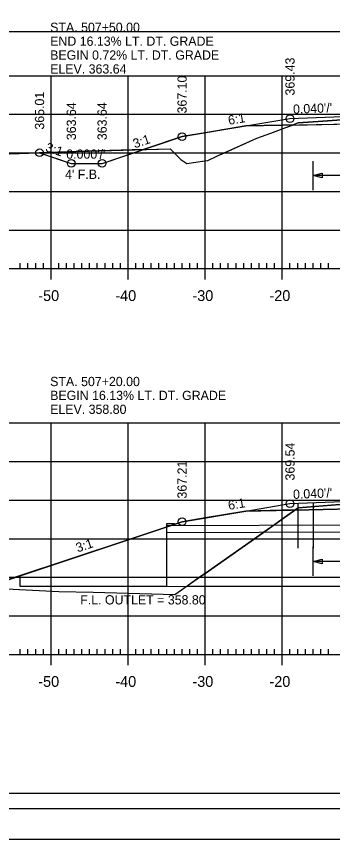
# Model space of a CAD drawing. Extents: x 1368910 to 1369601, y 380116 to 380950.
# Drawn here: x 1369025.7 to 1369066.8, y 380523.8 to 380630.4 of the extents above; entities that cross this region are included whole.
import ezdxf

# ---------------------------------------------------------------- set-up
doc = ezdxf.new("R2010")
doc.units = 0
for name, color, linetype in [('_STAGE 2 CUT', 7, 'Continuous'), ('_STAGE 2 FILL', 7, 'Continuous'), ('Notes', 7, 'Continuous'), ('R_Alt Surface', 7, 'Continuous'), ('R_Axis', 7, 'Continuous'), ('R_Axis Annot', 7, 'Continuous'), ('R_Border', 7, 'Continuous'), ('R_Detour', 7, 'Continuous'), ('R_Exist Surface', 7, 'Continuous'), ('R_Fin Surface', 7, 'Continuous'), ('R_Grid', 7, 'Continuous'), ('R_No Plot', 7, 'Continuous'), ('R_ROW Annot', 7, 'Continuous'), ('R_Water', 7, 'Continuous'), ('R_Xsect Elev', 7, 'Continuous'), ('R_Xsect Slope', 7, 'Continuous')]:
    doc.layers.add(name, color=color, linetype=linetype)

msp = doc.modelspace()

# ---------------------------------------------------------------- linework, layer by layer
at = {"layer": '_STAGE 2 CUT'}
for p, q in [((1369061.88, 380566.47), (1369060.24, 380565.31)), ((1369069.24, 380566.62), (1369061.88, 380566.47)), ((1369056.62, 380562.76), (1369050.24, 380558.27)), ((1369049.52, 380557.76), (1369047.88, 380556.6)), ((1369050.24, 380558.27), (1369049.52, 380557.76))]:
    msp.add_line(p, q, dxfattribs=at)
for points in [[(1369080.24, 380617.57), (1369079.42, 380617.53), (1369077.26, 380617.44), (1369076.31, 380617.43), (1369075.94, 380617.41), (1369072.39, 380617.32), (1369071.95, 380617.31), (1369071.59, 380617.29), (1369071, 380617.28), (1369070.24, 380617.22), (1369069.92, 380617.2), (1369069.74, 380617.18), (1369064.91, 380616.82), (1369062.29, 380616.63), (1369061.59, 380616.36)], [(1369061.59, 380616.36), (1369069.24, 380616.51), (1369070.24, 380616.53), (1369080.24, 380616.73)], [(1369042.22, 380613.19), (1369033.48, 380612.94), (1369028.74, 380612.77)], [(1369028.74, 380612.77), (1369028.78, 380612.76), (1369032.86, 380611.4), (1369036.86, 380611.4), (1369040.94, 380612.76), (1369042.22, 380613.19)], [(1369080.24, 380567.74), (1369075.74, 380567.58), (1369074.18, 380567.5), (1369073.93, 380567.49), (1369071.99, 380567.45), (1369070.24, 380567.37), (1369070.04, 380567.36), (1369069.89, 380567.35), (1369064.47, 380566.92), (1369062.3, 380566.75), (1369062.13, 380566.64), (1369061.88, 380566.47)], [(1369061.88, 380566.47), (1369069.24, 380566.62), (1369070.24, 380566.64), (1369080.24, 380566.84)], [(1369060.24, 380565.31), (1369059.26, 380564.62), (1369057.84, 380563.62), (1369056.62, 380562.76)], [(1369047.88, 380556.6), (1369050.24, 380556.61), (1369060.24, 380556.62), (1369070.24, 380556.64), (1369080.24, 380556.66)]]:
    msp.add_lwpolyline(points, dxfattribs=at)
at = {"layer": '_STAGE 2 FILL'}
for p, q in [((1369060.24, 380616.33), (1369055.52, 380616.24)), ((1369061.59, 380616.36), (1369060.24, 380616.33)), ((1369060.24, 380566.44), (1369055.52, 380566.34)), ((1369061.88, 380566.47), (1369060.24, 380566.44))]:
    msp.add_line(p, q, dxfattribs=at)
for points in [[(1369042.22, 380613.19), (1369045.71, 380613.28), (1369046.22, 380612.76), (1369047.07, 380611.89), (1369047.87, 380611.39), (1369050.2, 380611.74), (1369050.24, 380611.74), (1369050.56, 380611.76), (1369051.84, 380612.36), (1369052.73, 380612.76), (1369056.94, 380614.65), (1369058.77, 380615.3), (1369060.24, 380615.85), (1369061.59, 380616.36)], [(1369055.52, 380616.24), (1369050.24, 380615.36), (1369047.24, 380614.86), (1369042.22, 380613.19)], [(1369019.31, 380556.56), (1369021.84, 380556.39), (1369031.24, 380555.91), (1369035.71, 380555.81), (1369040.24, 380555.68), (1369046.32, 380555.51), (1369049.52, 380557.76), (1369050.24, 380558.27), (1369056.62, 380562.76), (1369060.24, 380565.31), (1369061.88, 380566.47)], [(1369055.52, 380566.34), (1369050.24, 380565.46), (1369047.24, 380564.96), (1369040.63, 380562.76), (1369040.24, 380562.63), (1369025.63, 380557.76), (1369022.03, 380556.56), (1369019.31, 380556.56)]]:
    msp.add_lwpolyline(points, dxfattribs=at)
at = {"layer": 'R_Alt Surface'}
for points in [[(1369055.52, 380616.24), (1369069.24, 380616.51), (1369080.24, 380616.73), (1369091.24, 380616.51), (1369104.97, 380616.24)], [(1369055.52, 380566.34), (1369069.24, 380566.62), (1369080.24, 380566.84), (1369091.24, 380566.62), (1369105.15, 380566.34)]]:
    msp.add_lwpolyline(points, dxfattribs=at)
at = {"layer": 'R_Axis'}
for p, q in [((1369030.24, 380596.36), (1369030.24, 380599.16)), ((1369040.24, 380596.36), (1369040.24, 380599.16)), ((1369050.24, 380596.36), (1369050.24, 380599.16)), ((1369060.24, 380596.36), (1369060.24, 380599.16)), ((1369026.24, 380597.76), (1369026.24, 380598.46)), ((1369027.24, 380597.76), (1369027.24, 380598.46)), ((1369028.24, 380597.76), (1369028.24, 380598.46)), ((1369029.24, 380597.76), (1369029.24, 380598.46)), ((1369031.24, 380597.76), (1369031.24, 380598.46)), ((1369032.24, 380597.76), (1369032.24, 380598.46)), ((1369033.24, 380597.76), (1369033.24, 380598.46)), ((1369034.24, 380597.76), (1369034.24, 380598.46)), ((1369035.24, 380597.76), (1369035.24, 380598.46)), ((1369036.24, 380597.76), (1369036.24, 380598.46)), ((1369037.24, 380597.76), (1369037.24, 380598.46)), ((1369038.24, 380597.76), (1369038.24, 380598.46)), ((1369039.24, 380597.76), (1369039.24, 380598.46)), ((1369041.24, 380597.76), (1369041.24, 380598.46)), ((1369042.24, 380597.76), (1369042.24, 380598.46)), ((1369043.24, 380597.76), (1369043.24, 380598.46)), ((1369044.24, 380597.76), (1369044.24, 380598.46)), ((1369045.24, 380597.76), (1369045.24, 380598.46)), ((1369046.24, 380597.76), (1369046.24, 380598.46)), ((1369047.24, 380597.76), (1369047.24, 380598.46)), ((1369048.24, 380597.76), (1369048.24, 380598.46)), ((1369049.24, 380597.76), (1369049.24, 380598.46)), ((1369051.24, 380597.76), (1369051.24, 380598.46)), ((1369052.24, 380597.76), (1369052.24, 380598.46)), ((1369053.24, 380597.76), (1369053.24, 380598.46)), ((1369054.24, 380597.76), (1369054.24, 380598.46)), ((1369055.24, 380597.76), (1369055.24, 380598.46)), ((1369056.24, 380597.76), (1369056.24, 380598.46)), ((1369057.24, 380597.76), (1369057.24, 380598.46)), ((1369058.24, 380597.76), (1369058.24, 380598.46)), ((1369059.24, 380597.76), (1369059.24, 380598.46)), ((1369061.24, 380597.76), (1369061.24, 380598.46)), ((1369062.24, 380597.76), (1369062.24, 380598.46)), ((1369063.24, 380597.76), (1369063.24, 380598.46)), ((1369064.24, 380597.76), (1369064.24, 380598.46)), ((1369065.24, 380597.76), (1369065.24, 380598.46)), ((1369066.24, 380597.76), (1369066.24, 380598.46)), ((1368940.24, 380597.76), (1369220.24, 380597.76)), ((1369030.24, 380546.36), (1369030.24, 380549.16)), ((1369040.24, 380546.36), (1369040.24, 380549.16)), ((1369050.24, 380546.36), (1369050.24, 380549.16)), ((1369060.24, 380546.36), (1369060.24, 380549.16)), ((1368940.24, 380547.76), (1369220.24, 380547.76)), ((1369026.24, 380547.76), (1369026.24, 380548.46)), ((1369027.24, 380547.76), (1369027.24, 380548.46)), ((1369028.24, 380547.76), (1369028.24, 380548.46)), ((1369029.24, 380547.76), (1369029.24, 380548.46)), ((1369031.24, 380547.76), (1369031.24, 380548.46)), ((1369032.24, 380547.76), (1369032.24, 380548.46)), ((1369033.24, 380547.76), (1369033.24, 380548.46)), ((1369034.24, 380547.76), (1369034.24, 380548.46)), ((1369035.24, 380547.76), (1369035.24, 380548.46)), ((1369036.24, 380547.76), (1369036.24, 380548.46)), ((1369037.24, 380547.76), (1369037.24, 380548.46)), ((1369038.24, 380547.76), (1369038.24, 380548.46)), ((1369039.24, 380547.76), (1369039.24, 380548.46)), ((1369041.24, 380547.76), (1369041.24, 380548.46)), ((1369042.24, 380547.76), (1369042.24, 380548.46)), ((1369043.24, 380547.76), (1369043.24, 380548.46)), ((1369044.24, 380547.76), (1369044.24, 380548.46)), ((1369045.24, 380547.76), (1369045.24, 380548.46)), ((1369046.24, 380547.76), (1369046.24, 380548.46)), ((1369047.24, 380547.76), (1369047.24, 380548.46)), ((1369048.24, 380547.76), (1369048.24, 380548.46)), ((1369049.24, 380547.76), (1369049.24, 380548.46)), ((1369051.24, 380547.76), (1369051.24, 380548.46)), ((1369052.24, 380547.76), (1369052.24, 380548.46)), ((1369053.24, 380547.76), (1369053.24, 380548.46)), ((1369054.24, 380547.76), (1369054.24, 380548.46)), ((1369055.24, 380547.76), (1369055.24, 380548.46)), ((1369056.24, 380547.76), (1369056.24, 380548.46)), ((1369057.24, 380547.76), (1369057.24, 380548.46)), ((1369058.24, 380547.76), (1369058.24, 380548.46)), ((1369059.24, 380547.76), (1369059.24, 380548.46)), ((1369061.24, 380547.76), (1369061.24, 380548.46)), ((1369062.24, 380547.76), (1369062.24, 380548.46)), ((1369063.24, 380547.76), (1369063.24, 380548.46)), ((1369064.24, 380547.76), (1369064.24, 380548.46)), ((1369065.24, 380547.76), (1369065.24, 380548.46)), ((1369066.24, 380547.76), (1369066.24, 380548.46))]:
    msp.add_line(p, q, dxfattribs=at)
at = {"layer": 'R_Border'}
msp.add_line((1369238.42, 380527.76), (1368922.24, 380527.76), dxfattribs=at)
at = {"layer": 'R_Detour'}
for p, q in [((1369062.24, 380567.36), (1369062.24, 380561.52)), ((1369064.24, 380567.36), (1369064.24, 380561.52))]:
    msp.add_line(p, q, dxfattribs=at)
at = {"layer": 'R_Exist Surface'}
for points in [[(1369016.21, 380612.32), (1369033.48, 380612.94), (1369045.71, 380613.28), (1369047.07, 380611.89), (1369047.87, 380611.39), (1369050.2, 380611.74), (1369050.56, 380611.76), (1369051.84, 380612.36), (1369056.94, 380614.65), (1369058.77, 380615.3), (1369062.29, 380616.63), (1369064.91, 380616.82), (1369069.74, 380617.18)], [(1369021.84, 380556.39), (1369031.24, 380555.91), (1369035.71, 380555.81), (1369046.32, 380555.51), (1369062.13, 380566.64), (1369062.3, 380566.75), (1369064.47, 380566.92), (1369069.89, 380567.35)]]:
    msp.add_lwpolyline(points, dxfattribs=at)
at = {"layer": 'R_Fin Surface'}
for points in [[(1369028.74, 380612.77), (1369032.86, 380611.4), (1369036.86, 380611.4), (1369047.24, 380614.86), (1369055.52, 380616.24), (1369061.24, 380617.19), (1369069.24, 380617.51), (1369080.24, 380617.73), (1369091.24, 380617.51), (1369099.24, 380617.19), (1369104.97, 380616.24), (1369113.24, 380614.86), (1369121.62, 380612.07), (1369121.63, 380612.07)], [(1369006.01, 380556.9), (1369007.03, 380556.56), (1369022.03, 380556.56), (1369047.24, 380564.96), (1369055.52, 380566.34), (1369061.24, 380567.3), (1369069.24, 380567.62), (1369080.24, 380567.84), (1369091.24, 380567.62), (1369099.24, 380567.3), (1369105.15, 380566.34), (1369113.24, 380565.03), (1369138.05, 380556.76), (1369153.05, 380556.76), (1369156.96, 380558.06)]]:
    msp.add_lwpolyline(points, dxfattribs=at)
at = {"layer": 'R_Grid'}
for p, q in [((1368940.24, 380622.76), (1369220.24, 380622.76)), ((1369030.24, 380597.76), (1369030.24, 380622.76)), ((1369040.24, 380597.76), (1369040.24, 380622.76)), ((1369050.24, 380597.76), (1369050.24, 380622.76)), ((1369060.24, 380597.76), (1369060.24, 380622.76)), ((1368940.24, 380617.76), (1369220.24, 380617.76)), ((1368940.24, 380612.76), (1369220.24, 380612.76)), ((1368940.24, 380607.76), (1369220.24, 380607.76)), ((1368940.24, 380602.76), (1369220.24, 380602.76)), ((1368940.24, 380597.76), (1369220.24, 380597.76)), ((1368940.24, 380577.76), (1369220.24, 380577.76)), ((1369030.24, 380547.76), (1369030.24, 380577.76)), ((1369040.24, 380547.76), (1369040.24, 380577.76)), ((1369050.24, 380547.76), (1369050.24, 380577.76)), ((1369060.24, 380547.76), (1369060.24, 380577.76)), ((1368940.24, 380572.76), (1369220.24, 380572.76)), ((1368940.24, 380567.76), (1369220.24, 380567.76)), ((1368940.24, 380562.76), (1369220.24, 380562.76)), ((1368940.24, 380557.76), (1369220.24, 380557.76)), ((1368940.24, 380552.76), (1369220.24, 380552.76)), ((1368940.24, 380547.76), (1369220.24, 380547.76))]:
    msp.add_line(p, q, dxfattribs=at)
at = {"layer": 'R_No Plot'}
for points in [[(1368909.84, 380737.11), (1369243.18, 380737.11), (1369243.18, 380523.78), (1368909.84, 380523.78)], [(1368924.24, 380731.22), (1369173.78, 380731.22), (1369173.78, 380721.34), (1369191.32, 380721.34), (1369215.42, 380721.34), (1369215.42, 380699.01), (1369236.42, 380699.01), (1369236.42, 380529.76), (1368924.24, 380529.76)], [(1368924.24, 380628.49), (1369236.42, 380628.49), (1369236.42, 380529.76), (1368924.24, 380529.76)]]:
    msp.add_lwpolyline(points, close=True, dxfattribs=at)
for centre in [(1369061.24, 380617.19), (1369047.24, 380614.86), (1369028.74, 380612.77), (1369032.86, 380611.4), (1369036.86, 380611.4), (1369061.24, 380567.3), (1369047.24, 380564.96)]:
    msp.add_circle(centre, 0.5, dxfattribs=at)
at = {"layer": 'R_ROW Annot'}
for p, q in [((1369064.24, 380607.93), (1369064.24, 380611.69)), ((1369076.24, 380609.81), (1369064.24, 380609.81)), ((1369064.24, 380557.93), (1369064.24, 380561.69)), ((1369076.24, 380559.81), (1369064.24, 380559.81))]:
    msp.add_line(p, q, dxfattribs=at)
for points in [[(1369065.44, 380609.51), (1369064.24, 380609.81), (1369065.44, 380610.11)], [(1369065.44, 380559.51), (1369064.24, 380559.81), (1369065.44, 380560.11)]]:
    msp.add_lwpolyline(points, close=True, dxfattribs=at)
at = {"layer": 'R_Water'}
for p, q in [((1369045.24, 380564.48), (1369115.24, 380564.68)), ((1369045.24, 380563.56), (1369115.24, 380563.76)), ((1369045.24, 380556.56), (1369115.24, 380556.76))]:
    msp.add_line(p, q, dxfattribs=at)
for points in [[(1369045.24, 380556.56), (1369045.24, 380563.56), (1369045.24, 380564.48), (1369045.24, 380564.73), (1369046.24, 380564.73), (1369046.24, 380564.48)], [(1369045.24, 380556.56), (1369026.24, 380556.56), (1369026.24, 380557.96)]]:
    msp.add_lwpolyline(points, dxfattribs=at)

# ---------------------------------------------------------------- texts
at = {"layer": 'Notes'}
for s, p in [('STA. 507+50.00', (1369030.12, 380628.43)), ('END 16.13% LT. DT. GRADE', (1369030.12, 380626.63)), ('BEGIN 0.72% LT. DT. GRADE', (1369030.12, 380624.83)), ('ELEV. 363.64', (1369030.12, 380623.03)), ('STA. 507+20.00', (1369030.12, 380582.53)), ('BEGIN 16.13% LT. DT. GRADE', (1369030.12, 380580.73)), ('ELEV. 358.80', (1369030.12, 380578.93))]:
    msp.add_text(s, height=1.2, dxfattribs=at).set_placement(p)
at = {"layer": 'R_Axis Annot'}
for s, p in [('-50', (1369028.58, 380593.56)), ('-40', (1369038.58, 380593.56)), ('-30', (1369048.58, 380593.56)), ('-20', (1369058.58, 380593.56)), ('-50', (1369028.58, 380543.56)), ('-40', (1369038.58, 380543.56)), ('-30', (1369048.58, 380543.56)), ('-20', (1369058.58, 380543.56))]:
    msp.add_text(s, height=1.4, dxfattribs=at).set_placement(p)
at = {"layer": 'R_Xsect Elev'}
for s, p in [('369.43', (1369061.84, 380620.19)), ('367.10', (1369047.84, 380617.86)), ('365.01', (1369029.34, 380615.77)), ('363.64', (1369033.46, 380614.4)), ('363.64', (1369037.46, 380614.4)), ('369.54', (1369061.84, 380570.3)), ('367.21', (1369047.84, 380567.96))]:
    msp.add_text(s, height=1.2, rotation=90, dxfattribs=at).set_placement(p)
at = {"layer": 'R_Xsect Slope'}
for s, rotation, p in [("0.040'/'", 2.2906, (1369061.66, 380617.81)), ('6:1', 9.4623, (1369053.31, 380616.38)), ('3:1', 18.4349, (1369041.1, 380613.34)), ('3:1', 341.5651, (1369029.43, 380612.99)), ("0.000'/'", 360, (1369032.21, 380612)), ("4' F.B.", 360, (1369032.06, 380609.38)), ("0.040'/'", 2.2906, (1369061.66, 380567.91)), ('6:1', 9.4623, (1369053.31, 380566.48)), ('3:1', 18.4349, (1369033.69, 380560.97)), ('F.L. OUTLET = 358.80', 360, (1369034.02, 380554.24))]:
    msp.add_text(s, height=1.2, rotation=rotation, dxfattribs=at).set_placement(p)

doc.saveas('drawing.dxf')
